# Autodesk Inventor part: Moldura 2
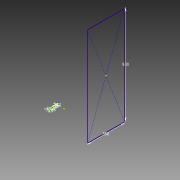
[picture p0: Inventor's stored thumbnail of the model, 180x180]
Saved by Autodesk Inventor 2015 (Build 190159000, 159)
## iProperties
Created: 2015-04
Part Number: Moldura 2
Material: Generic
Document SubType Name: Modeling
Designer: suporte
Density: 1 g/cm^3
Appearance: Default
Author: suporte
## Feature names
1. Sweep1
## Parameters: d2 = 85 mm, d3 = 8 mm, d4 = 5 mm, d5 = 25 mm, d7 = 35 mm, d8 = 5 mm, d9 = 7 mm, d10 = 23 mm, d11 = 0, d12 = 0
